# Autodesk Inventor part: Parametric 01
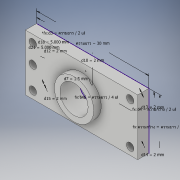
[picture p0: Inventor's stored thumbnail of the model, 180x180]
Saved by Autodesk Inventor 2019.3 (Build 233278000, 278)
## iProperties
Created: 2019-02
Part Number: Parametric 01
Material: Generic
Document SubType Name: Modeling
Designer: Synergysoft
Density: 1 g/cm^3
Appearance: Default
Author: Synergysoft
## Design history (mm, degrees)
sketch "Sketch1"
  geometry: L1 (0, 0)-(30, 0); L2 (30, 0)-(30, 15); L3 (30, 15)-(0, 15); L4 (0, 15)-(0, 0); L5 (2, 13)-(28, 13); L6 (28, 13)-(28, 2); L7 (28, 2)-(2, 2); L8 (2, 2)-(2, 13); C1 r 3.75 at (15, 7.5); C2 r 5.25 at (15, 7.5); C3 r 1 at (2, 13); C4 r 1 at (28, 13); C5 r 1 at (28, 2); C6 r 1 at (2, 2); C7 r 1 at (7, 13); C8 r 1 at (12, 13); C9 r 1 at (17, 13); C10 r 1 at (22, 13); C11 r 1 at (2, 8); C12 r 1 at (7, 8); C13 r 1 at (12, 8); C14 r 1 at (17, 8); C15 r 1 at (22, 8)
  constraints: 16 end point, 15 centre point, 4 parallel, 2 horizontal, 2 perpendicular, 1 coincident, 1 horizontal alignment, 1 vertical, 1 vertical alignment, 22 other
  dimensions: "d3" = 15 distance from line of C1.centre L4 (derived); "d4" = 7.5 distance from line of C1.centre L3 (derived); "d7" = 1.5 radial gap between concentric circles of C1 C2; "d10" = 2 distance between parallel lines of L3 L5; "d12" = 2 diameter of C3; "d13" = 2 diameter of C4; "d14" = 2 diameter of C5; "d15" = 2 diameter of C6; "d18" = 5 distance of C3.centre C7.centre; "d21" = 5 distance of C3.centre C11.centre
extrude "Extrusion1" new body sketch "Sketch1" distance "d5" = 3 (derived); taper "d6" = 0 deg
extrude "Extrusion2" join sketch "Sketch1" distance "d8" = 5; taper "d9" = 0 deg
extrude "Extrusion3" cut sketch "Sketch1" distance "d24" = 5; taper "d25" = 0 deg
body "Solid1"
